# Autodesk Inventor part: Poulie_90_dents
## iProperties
Created: 2011-01
Part Number: Poulie_90_dents
Document SubType Name: Modeling
Designer: eric
Density: 1 g/cm^3
Mass: 28.7836 g
Surface Area: 132.93 cm^2
Volume: 28.7836 cm^3
Author: eric
